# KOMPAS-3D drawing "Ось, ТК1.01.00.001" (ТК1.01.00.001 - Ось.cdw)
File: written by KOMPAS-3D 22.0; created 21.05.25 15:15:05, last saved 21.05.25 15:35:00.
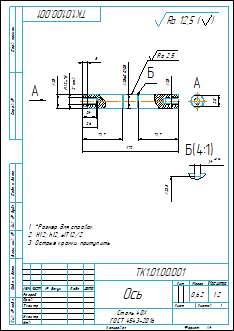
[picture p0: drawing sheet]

Sheet 1: A4, portrait

Document properties: Автор: user; Знак неуказанной шероховатости: 4; Параметр неуказанной шероховатости: Ra 12,5; Масса: 0.62382

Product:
- Body: Тело 8
    Материал: Сталь 40Х ГОСТ 4543-2016 (density 7850 kg/m3)
- Part/product: Ось  | designation ТК1.01.00.001
    Материал: Сталь 40Х ГОСТ 4543-2016 (density 7850 kg/m3)
    Масса: 0.62382
    Форматы листов документа: A4

Title block, sheet 1: Наименование: Ось; designation: ТК1.01.00.001; Материал: Сталь 40Х / ГОСТ 4543-2016; Масса: 0,62; Количество листов документа: 1; Форматы листов документа: A4; stored path: D:\Рабочая папка\АРХИВ\612\05\Задание №6 - Тележка для крыши\3Д\Тележка в сборе\ТК1.01.00.001 - Ось.cdw

Views: Проекционный вид 4, Местный разрез 1, Местный разрез 2, Выносной элемент 5, Вид по стрелке 6, Выносной элемент Б, Выносной элемент, Вид по стрелке А
Referenced files in D:\Рабочая папка\АРХИВ\612\05\Задание №6 - Тележка для крыши\3Д\Тележка в сборе\: Ось.m3d
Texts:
  js7
  Ra 2,5
  Ra 12,5
  Ra 12,5 ( )
  BOSimple***Material:5b3b2396-5625-11d7-8827-00508b01a93a
  ТК1.01.00.001 Ось
Dimensions and other numbers on the sheet: 172; 71,7; 25±0,0105; 26; 24; -7Н; 12; 2 отв.; 8; 1,4; 23,5; 20; 1:2; 1; 0,62

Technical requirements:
  *Размер для справок.
  H12, h12, ±IT12/2.
  Острые кромки притупить.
